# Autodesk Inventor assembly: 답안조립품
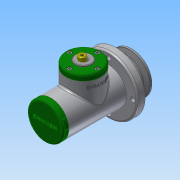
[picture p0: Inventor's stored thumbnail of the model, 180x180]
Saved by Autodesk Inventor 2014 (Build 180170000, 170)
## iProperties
Created: 2016-08
Part Number: 답안조립품
Document SubType Name: Assembly
Designer: 703
Author: 703
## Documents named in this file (24)
- C:\Users\703\Desktop\460807V1018\답안조립품.iam
- C:\Users\703\Desktop\460807V1018\본체.ipt
- C:\Users\703\Desktop\460807V1018\편심축.ipt
- C:\Users\703\Desktop\460807V1018\링크.ipt
- C:\Users\703\Desktop\460807V1018\부시1.ipt
- C:\Users\703\Desktop\460807V1018\베어링 15 x 35 x 11.ipt
- C:\Users\703\Desktop\460807V1018\멈춤링 15 x 1.ipt
- C:\Users\703\Desktop\460807V1018\멈춤링 35x1.6.ipt
- C:\Users\703\Desktop\460807V1018\부시2.ipt
- C:\Users\703\Desktop\460807V1018\와셔 10x21.ipt
- C:\Users\703\Desktop\460807V1018\너트 M10.ipt
- C:\Users\703\Desktop\460807V1018\사이드 커버.ipt
- 사이드 커버.ipt
- C:\Users\703\Desktop\460807V1018\키 4 x 4 x 18.ipt
- C:\Users\703\Desktop\460807V1018\V-벨트풀리.ipt
- C:\Users\703\Desktop\460807V1018\와셔 4x16.ipt
- C:\Users\703\Desktop\460807V1018\볼트 M4 x 10.ipt
- C:\Users\703\Desktop\460807V1018\클래스터 핀 6 x 24.ipt
- C:\Users\703\Desktop\460807V1018\슬라이더.ipt
- C:\Users\703\Desktop\460807V1018\탑 커버.ipt
- 탑 커버.ipt
- C:\Users\703\Desktop\460807V1018\탑 부시.ipt
- C:\Users\703\Desktop\460807V1018\볼트 M4 x 12.ipt
- C:\Users\703\Desktop\460807V1018\분할핀 1.6 x 12.ipt
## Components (6 placed, 3 different names)
1. V-벨트풀리:1 — 각도:2
2. ISO 4017 M4 x 10:1
3. ISO 4762 M4 x 12:1
4. ISO 4762 M4 x 12:2
5. ISO 4762 M4 x 12:3
6. ISO 4762 M4 x 12:4
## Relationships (1: Angle 1)
- 각도:2 [Angle]: V-벨트풀리:1
